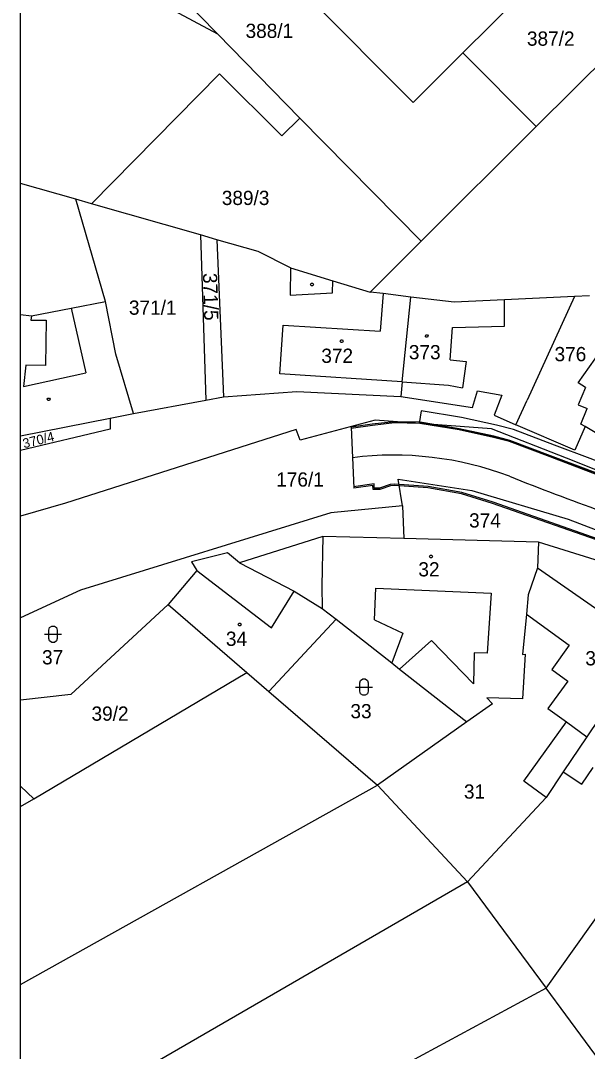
# Model space of a CAD drawing. Extents: x -639621 to -639329, y -1192893 to -1192488.
# Drawn here: x -639621.3 to -639553.5, y -1192770.8 to -1192647.6 of the extents above; entities that cross this region are included whole.
import ezdxf

# ---------------------------------------------------------------- set-up
doc = ezdxf.new("R2010")
doc.units = 0
for name, color, linetype in [('Vrstva 1', 7, 'Continuous'), ('Vrstva 19', 7, 'Continuous'), ('Vrstva 2', 7, 'Continuous'), ('Vrstva 20', 7, 'Continuous'), ('Vrstva 3', 7, 'Continuous'), ('Vrstva 4', 7, 'Continuous'), ('Vrstva 5', 7, 'Continuous'), ('Vrstva 61', 7, 'Continuous')]:
    doc.layers.add(name, color=color, linetype=linetype)

msp = doc.modelspace()

# ---------------------------------------------------------------- linework, layer by layer
at = {"layer": 'Vrstva 1'}
for p, q in [((-639597.73, -1192649.2), (-639609.37, -1192637.29)), ((-639555.01, -1192638.16), (-639568.41, -1192651.47)), ((-639613.04, -1192640.98), (-639597.73, -1192649.2)), ((-639559.67, -1192660.27), (-639546.32, -1192646.99)), ((-639587.88, -1192659.28), (-639597.73, -1192649.2)), ((-639568.41, -1192651.47), (-639559.67, -1192660.27)), ((-639597.48, -1192653.95), (-639612.81, -1192669.48)), ((-639590.06, -1192661.39), (-639597.48, -1192653.95)), ((-639587.88, -1192659.28), (-639590.06, -1192661.39)), ((-639573.4, -1192673.94), (-639587.88, -1192659.28)), ((-639573.4, -1192673.94), (-639559.67, -1192660.27)), ((-639614.68, -1192668.95), (-639621.26, -1192667.06)), ((-639611.11, -1192681.16), (-639614.68, -1192668.95)), ((-639612.81, -1192669.48), (-639614.68, -1192668.95)), ((-639599.75, -1192673.22), (-639612.81, -1192669.48)), ((-639599.75, -1192673.22), (-639599.11, -1192692.94)), ((-639597.81, -1192673.78), (-639599.75, -1192673.22)), ((-639597.81, -1192673.78), (-639597.01, -1192692.55)), ((-639592.87, -1192675.19), (-639597.81, -1192673.78)), ((-639579.49, -1192680.04), (-639573.4, -1192673.94)), ((-639589.03, -1192677.15), (-639592.87, -1192675.19)), ((-639589.03, -1192677.15), (-639583.94, -1192678.69)), ((-639583.94, -1192678.69), (-639579.49, -1192680.04)), ((-639577.94, -1192680.23), (-639579.49, -1192680.04)), ((-639615.21, -1192681.95), (-639611.11, -1192681.16)), ((-639609.89, -1192687.46), (-639611.11, -1192681.16)), ((-639574.65, -1192680.63), (-639577.94, -1192680.23)), ((-639575.67, -1192690.77), (-639574.65, -1192680.63)), ((-639569.45, -1192681.26), (-639574.65, -1192680.63)), ((-639563.42, -1192680.98), (-639569.45, -1192681.26)), ((-639555.06, -1192680.58), (-639563.42, -1192680.98)), ((-639555.06, -1192680.58), (-639560.72, -1192692.94)), ((-639553.28, -1192680.5), (-639555.06, -1192680.58)), ((-639619.98, -1192682.86), (-639615.21, -1192681.95)), ((-639621.26, -1192682.71), (-639619.98, -1192682.86)), ((-639554.62, -1192690.9), (-639551.25, -1192686.09)), ((-639607.78, -1192694.54), (-639609.89, -1192687.46)), ((-639575.67, -1192690.77), (-639575.84, -1192692.5)), ((-639553.78, -1192691.45), (-639554.62, -1192690.9)), ((-639597.01, -1192692.55), (-639588.26, -1192691.91)), ((-639588.26, -1192691.91), (-639575.84, -1192692.5)), ((-639567.27, -1192693.83), (-639566.65, -1192691.83)), ((-639566.65, -1192691.83), (-639563.75, -1192692.37)), ((-639563.75, -1192692.37), (-639564.69, -1192694.76)), ((-639553.78, -1192691.45), (-639554.63, -1192693.5)), ((-639607.78, -1192694.54), (-639599.11, -1192692.94)), ((-639599.11, -1192692.94), (-639597.01, -1192692.55)), ((-639575.84, -1192692.5), (-639567.27, -1192693.83)), ((-639562.08, -1192695.91), (-639560.72, -1192692.94)), ((-639554.63, -1192693.5), (-639553.55, -1192693.95)), ((-639610.58, -1192695.1), (-639607.78, -1192694.54)), ((-639564.69, -1192694.76), (-639562.08, -1192695.91)), ((-639554.32, -1192695.81), (-639553.55, -1192693.95)), ((-639621.26, -1192697.22), (-639610.58, -1192695.1)), ((-639610.58, -1192695.1), (-639610.55, -1192696.43)), ((-639578.89, -1192695.35), (-639587.87, -1192697.73)), ((-639564.99, -1192696.36), (-639578.89, -1192695.35)), ((-639555.03, -1192698.94), (-639562.08, -1192695.91)), ((-639553.81, -1192696.1), (-639555.03, -1192698.94)), ((-639553.81, -1192696.1), (-639554.32, -1192695.81)), ((-639552.6, -1192696.8), (-639553.81, -1192696.1)), ((-639610.55, -1192696.43), (-639621.26, -1192698.97)), ((-639588.35, -1192696.45), (-639615.89, -1192705.25)), ((-639587.87, -1192697.73), (-639588.35, -1192696.45)), ((-639556.03, -1192699.88), (-639564.99, -1192696.36)), ((-639536.13, -1192707.8), (-639556.03, -1192699.88)), ((-639575.61, -1192705.56), (-639576.14, -1192702.41)), ((-639576.14, -1192702.41), (-639567.36, -1192703.76)), ((-639567.36, -1192703.76), (-639555.84, -1192707.16)), ((-639615.89, -1192705.25), (-639621.26, -1192706.81)), ((-639575.61, -1192705.56), (-639584.19, -1192706.43)), ((-639575.61, -1192705.56), (-639575.47, -1192709.49)), ((-639584.19, -1192706.43), (-639614.09, -1192715.64)), ((-639555.84, -1192707.16), (-639520.25, -1192720.87)), ((-639585.15, -1192709.25), (-639595.09, -1192712.38)), ((-639575.47, -1192709.49), (-639585.15, -1192709.25)), ((-639559.39, -1192709.9), (-639575.47, -1192709.49)), ((-639559.39, -1192709.9), (-639559.48, -1192712.99)), ((-639552.59, -1192712.04), (-639559.39, -1192709.9)), ((-639596.55, -1192711.19), (-639600.86, -1192712.26)), ((-639595.09, -1192712.38), (-639596.55, -1192711.19)), ((-639600.2, -1192713.3), (-639603.63, -1192717.36)), ((-639600.86, -1192712.26), (-639600.2, -1192713.3)), ((-639595.09, -1192712.38), (-639588.59, -1192715.79)), ((-639559.48, -1192712.99), (-639560.6, -1192716.22)), ((-639614.09, -1192715.64), (-639621.26, -1192718.97)), ((-639588.59, -1192715.79), (-639585.21, -1192717.84)), ((-639560.6, -1192716.22), (-639560.83, -1192718.54)), ((-639603.63, -1192717.36), (-639615.25, -1192728.1)), ((-639603.63, -1192717.36), (-639594.22, -1192725.5)), ((-639585.21, -1192717.84), (-639583.57, -1192719.13)), ((-639583.57, -1192719.13), (-639591.6, -1192727.76)), ((-639583.57, -1192719.13), (-639576.92, -1192724.35)), ((-639560.83, -1192718.54), (-639561.29, -1192723.32)), ((-639560.83, -1192718.54), (-639555.71, -1192722.22)), ((-639555.71, -1192722.22), (-639557.8, -1192725.14)), ((-639546.26, -1192722.22), (-639553.6, -1192733.16)), ((-639576.92, -1192724.35), (-639575.99, -1192725.08)), ((-639561.29, -1192723.32), (-639560.98, -1192723.31)), ((-639560.98, -1192723.31), (-639561.27, -1192728.63)), ((-639619.69, -1192740.58), (-639594.22, -1192725.5)), ((-639594.22, -1192725.5), (-639591.6, -1192727.76)), ((-639575.99, -1192725.08), (-639567.94, -1192731.4)), ((-639557.8, -1192725.14), (-639555.88, -1192726.52)), ((-639555.88, -1192726.52), (-639558.25, -1192729.81)), ((-639615.25, -1192728.1), (-639621.26, -1192728.78)), ((-639591.6, -1192727.76), (-639578.63, -1192738.96)), ((-639564.87, -1192729.23), (-639567.94, -1192731.4)), ((-639561.27, -1192728.63), (-639565.56, -1192728.52)), ((-639565.56, -1192728.52), (-639564.87, -1192729.23)), ((-639558.25, -1192729.81), (-639556.04, -1192731.4)), ((-639567.94, -1192731.4), (-639578.63, -1192738.96)), ((-639561.14, -1192738.49), (-639556.04, -1192731.4)), ((-639553.6, -1192733.16), (-639556.41, -1192737.34)), ((-639556.41, -1192737.34), (-639558.48, -1192740.42)), ((-639621.26, -1192762.78), (-639578.63, -1192738.96)), ((-639621.26, -1192739.05), (-639619.69, -1192740.58)), ((-639578.63, -1192738.96), (-639567.88, -1192750.5)), ((-639558.48, -1192740.42), (-639561.14, -1192738.49)), ((-639558.48, -1192740.42), (-639567.88, -1192750.5)), ((-639621.26, -1192741.51), (-639619.69, -1192740.58)), ((-639567.88, -1192750.5), (-639621.26, -1192781.4)), ((-639567.88, -1192750.5), (-639558.48, -1192763.2)), ((-639558.48, -1192763.2), (-639551.56, -1192753.52)), ((-639558.48, -1192763.2), (-639621.26, -1192797.12)), ((-639551.4, -1192772.76), (-639558.48, -1192763.2))]:
    msp.add_line(p, q, dxfattribs=at)
at = {"layer": 'Vrstva 19'}
for p, q in [((-639568.84, -1192696.36), (-639564.71, -1192697.26)), ((-639564.71, -1192697.26), (-639562.79, -1192697.76)), ((-639562.79, -1192697.76), (-639557.93, -1192699.59)), ((-639557.93, -1192699.59), (-639553.67, -1192701.21)), ((-639553.67, -1192701.21), (-639539.17, -1192706.72)), ((-639579.16, -1192703.13), (-639581.46, -1192703.45)), ((-639579.14, -1192703.63), (-639579.16, -1192703.13)), ((-639577.08, -1192703.17), (-639578.34, -1192703.63)), ((-639576.59, -1192703.15), (-639577.08, -1192703.17)), ((-639572.59, -1192703.42), (-639576.59, -1192703.15)), ((-639568.56, -1192704.13), (-639572.59, -1192703.42)), ((-639578.34, -1192703.63), (-639579.14, -1192703.63)), ((-639564.86, -1192705.28), (-639568.56, -1192704.13)), ((-639541.9, -1192713.36), (-639564.86, -1192705.28))]:
    msp.add_line(p, q, dxfattribs=at)
for points in [[(-639573.62, -1192695.58), (-639576.61, -1192695.53), (-639579.25, -1192695.84), (-639581.77, -1192696.18), (-639581.46, -1192703.45)], [(-639576.6, -1192695.68), (-639579.23, -1192695.99), (-639581.75, -1192696.33)], [(-639539.22, -1192706.86), (-639553.73, -1192701.35), (-639557.98, -1192699.73), (-639562.84, -1192697.9), (-639564.75, -1192697.41), (-639568.87, -1192696.51), (-639573.54, -1192695.73), (-639576.6, -1192695.68)], [(-639541.85, -1192713.22), (-639564.81, -1192705.14), (-639568.53, -1192703.98), (-639572.57, -1192703.27), (-639576.59, -1192703), (-639577.11, -1192703.02), (-639578.37, -1192703.48), (-639579, -1192703.48), (-639579.02, -1192702.96), (-639581.47, -1192703.3)]]:
    msp.add_lwpolyline(points, dxfattribs=at)
for centre, radius, start, end in [((-639576.66, -1192738.58), 39.06, 69.3045, 97.2869), ((-639433.01, -1192376.65), 350.34, 248.2466, 252.0948)]:
    msp.add_arc(centre, radius, start, end, dxfattribs=at)
at = {"layer": 'Vrstva 20'}
msp.add_line((-639573.52, -1192695.58), (-639568.84, -1192696.36), dxfattribs=at)
for points in [[(-639543.08, -1192703.79), (-639553.2, -1192699.94), (-639557.45, -1192698.33), (-639562.38, -1192696.47), (-639564.4, -1192695.95), (-639568.59, -1192695.04), (-639573.4, -1192694.23), (-639573.65, -1192695.73)], [(-639539.17, -1192706.72), (-639553.67, -1192701.21), (-639557.93, -1192699.59), (-639562.79, -1192697.76), (-639564.71, -1192697.26), (-639568.84, -1192696.36), (-639573.53, -1192695.58), (-639573.62, -1192695.58)]]:
    msp.add_lwpolyline(points, dxfattribs=at)
at = {"layer": 'Vrstva 3'}
for points in [[(-639617.89, -1192720.42), (-639617.79, -1192720.13), (-639617.54, -1192719.95), (-639617.23, -1192719.95), (-639616.98, -1192720.13), (-639616.88, -1192720.42), (-639616.88, -1192721.42), (-639616.98, -1192721.71), (-639617.23, -1192721.89), (-639617.54, -1192721.89), (-639617.79, -1192721.71), (-639617.89, -1192721.42)], [(-639580.73, -1192726.73), (-639580.63, -1192726.44), (-639580.38, -1192726.26), (-639580.07, -1192726.26), (-639579.82, -1192726.44), (-639579.72, -1192726.73), (-639579.72, -1192727.73), (-639579.82, -1192728.02), (-639580.07, -1192728.2), (-639580.38, -1192728.2), (-639580.63, -1192728.02), (-639580.73, -1192727.73)]]:
    msp.add_lwpolyline(points, close=True, dxfattribs=at)
for points in [[(-639618.39, -1192720.92), (-639617.12, -1192720.92), (-639616.39, -1192720.92)], [(-639581.23, -1192727.23), (-639579.96, -1192727.23), (-639579.23, -1192727.23)]]:
    msp.add_lwpolyline(points, dxfattribs=at)
at = {"layer": 'Vrstva 4'}
for p, q in [((-639574.37, -1192657.4), (-639601.86, -1192629.73)), ((-639568.41, -1192651.47), (-639574.37, -1192657.4)), ((-639589.03, -1192677.15), (-639589.07, -1192680.4)), ((-639583.99, -1192680.15), (-639583.94, -1192678.69)), ((-639589.07, -1192680.4), (-639583.99, -1192680.15)), ((-639577.94, -1192680.23), (-639578.28, -1192684.7)), ((-639563.42, -1192684.11), (-639563.42, -1192680.98)), ((-639615.21, -1192681.95), (-639613.48, -1192689.67)), ((-639619.98, -1192682.86), (-639620.04, -1192683.4)), ((-639620.04, -1192683.4), (-639618.21, -1192683.38)), ((-639618.21, -1192683.38), (-639618.3, -1192688.81)), ((-639590.28, -1192689.81), (-639589.88, -1192684.01)), ((-639589.88, -1192684.01), (-639578.28, -1192684.7)), ((-639569.93, -1192688.15), (-639569.66, -1192684.29)), ((-639569.66, -1192684.29), (-639563.42, -1192684.11)), ((-639620.64, -1192688.77), (-639620.93, -1192691.34)), ((-639618.3, -1192688.81), (-639620.64, -1192688.77)), ((-639569.93, -1192688.15), (-639568.01, -1192688.35)), ((-639568.01, -1192688.35), (-639568.45, -1192691.49)), ((-639620.93, -1192691.34), (-639613.48, -1192689.67)), ((-639575.67, -1192690.77), (-639590.28, -1192689.81)), ((-639575.67, -1192690.77), (-639570.15, -1192691.17)), ((-639570.15, -1192691.17), (-639568.45, -1192691.49)), ((-639585.15, -1192709.25), (-639585.26, -1192715.14)), ((-639600.2, -1192713.3), (-639591.29, -1192720.15)), ((-639559.48, -1192712.99), (-639546.26, -1192722.22)), ((-639591.29, -1192720.15), (-639588.59, -1192715.79)), ((-639585.26, -1192715.14), (-639585.21, -1192717.84)), ((-639578.98, -1192719.18), (-639578.82, -1192715.42)), ((-639578.82, -1192715.42), (-639565.04, -1192716.02)), ((-639565.04, -1192716.02), (-639565.53, -1192723.19)), ((-639578.98, -1192719.18), (-639575.58, -1192720.81)), ((-639575.58, -1192720.81), (-639576.92, -1192724.35)), ((-639575.99, -1192725.08), (-639572.17, -1192721.67)), ((-639572.17, -1192721.67), (-639567.16, -1192726.86)), ((-639567.05, -1192723.15), (-639567.16, -1192726.86)), ((-639565.53, -1192723.19), (-639567.05, -1192723.15)), ((-639556.04, -1192731.4), (-639553.6, -1192733.16)), ((-639556.41, -1192737.34), (-639554.18, -1192738.84)), ((-639554.18, -1192738.84), (-639552.83, -1192736.83))]:
    msp.add_line(p, q, dxfattribs=at)
at = {"layer": 'Vrstva 5'}
for points in [[(-639586.36, -1192678.99), (-639586.27, -1192679.14), (-639586.36, -1192679.29), (-639586.54, -1192679.29), (-639586.63, -1192679.14), (-639586.54, -1192678.99)], [(-639582.8, -1192685.75), (-639582.71, -1192685.9), (-639582.8, -1192686.05), (-639582.98, -1192686.05), (-639583.07, -1192685.9), (-639582.98, -1192685.75)], [(-639572.64, -1192685.13), (-639572.55, -1192685.28), (-639572.64, -1192685.43), (-639572.82, -1192685.43), (-639572.91, -1192685.28), (-639572.82, -1192685.13)], [(-639617.82, -1192692.7), (-639617.73, -1192692.85), (-639617.82, -1192693), (-639618, -1192693), (-639618.09, -1192692.85), (-639618, -1192692.7)], [(-639572.14, -1192711.48), (-639572.05, -1192711.63), (-639572.14, -1192711.78), (-639572.32, -1192711.78), (-639572.41, -1192711.63), (-639572.32, -1192711.48)], [(-639595.01, -1192719.61), (-639594.92, -1192719.76), (-639595.01, -1192719.91), (-639595.19, -1192719.91), (-639595.28, -1192719.76), (-639595.19, -1192719.61)]]:
    msp.add_lwpolyline(points, close=True, dxfattribs=at)
at = {"layer": 'Vrstva 61'}
msp.add_lwpolyline([(-639621.26, -1192893.33), (-639621.26, -1192487.83)], dxfattribs=at)

# ---------------------------------------------------------------- texts
at = {"layer": 'Vrstva 2'}
for s, p in [('388/1', (-639594.38, -1192649.68)), ('387/2', (-639560.76, -1192650.61)), ('389/3', (-639597.22, -1192669.64)), ('371/1', (-639608.32, -1192682.75)), ('372', (-639585.33, -1192688.5)), ('373', (-639574.87, -1192688.07)), ('376', (-639557.46, -1192688.3)), ('176/1', (-639590.72, -1192703.28)), ('374', (-639567.67, -1192708.17)), ('32', (-639573.73, -1192714.01)), ('34', (-639596.73, -1192722.31)), ('37', (-639618.7, -1192724.52)), ('30', (-639553.78, -1192724.64)), ('33', (-639581.85, -1192730.96)), ('39/2', (-639612.79, -1192731.25)), ('31', (-639568.29, -1192740.56))]:
    msp.add_text(s, height=1.7, dxfattribs=at).set_placement(p)
for s, height, rotation, p in [('371/5', 1.7, 271.6393, (-639599.48, -1192677.78)), ('370/4', 1.14, 13.9802, (-639620.85, -1192698.72))]:
    msp.add_text(s, height=height, rotation=rotation, dxfattribs=at).set_placement(p)

doc.saveas('drawing.dxf')
